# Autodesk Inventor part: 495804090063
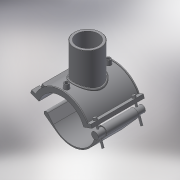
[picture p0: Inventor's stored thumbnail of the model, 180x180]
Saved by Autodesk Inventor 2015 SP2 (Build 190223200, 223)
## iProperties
Created: 2017-07
Part Number: 495804090063
Material: Generic
Description: PLASSON BRANCH SADDLE 90-63
Document SubType Name: Modeling
Designer: KIM
Density: 1 g/cm^3
Appearance: Default
Author: KIM
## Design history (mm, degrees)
derived "495804.ipt"
feature "Solid1::495804.ipt"
feature "Solid2::495804.ipt"
tag "TaggingFeature1"
body "Solid1"
body "Solid2"
other parameters: "d2" = 126, "d3" = 22.5, "d4" = 118, "d5" = 0, "d6" = 0.1, "d8" = 0, "d19" = 6, "d20" = 6, "d21" = 70.8, "d23" = 0, "d24" = 35.4, "d26" = 0, "d27" = 3, "d28" = 3, "d29" = 3, "d31" = 6, "d32" = 0, "d33" = 0, "d34" = 0.6, "d40" = 56.16, "d41" = 69.3, "d43" = 0, "d45" = 0, "d47" = 148, "d48" = 63, "d50" = 0, "d70" = 15, "d72" = 0, "d73" = 6, "d75" = 5, "d76" = 0, "d77" = 4.5, "d78" = 75, "d79" = 15, "d80" = 47.2, "d82" = 5 deg, "d84" = 4, "d85" = 14, "d86" = 0, "d87" = 3, "d88" = 0, "d89" = 1, "d90" = 1, "d91" = 94.4, "d92" = 0, "d93" = 0.5, "d94" = 47.36842, "d96" = 110.16, "d97" = 2.36, "d98" = 0, "d102" = 1.89, "d103" = 50.4, "d105" = 0, "d109" = -31.33333, "d117" = 0.63, "d120" = 140 deg, "d121" = 24.228, "d122" = 20 deg, "d123" = 216, "d124" = 64.8, "d126" = 0, "d143" = 94.5, "d150" = 16.2, "d159" = 3.6, "d161" = 2.25, "d162" = 70.8, "d163" = 0, "d167" = 18, "d168" = 49.09091, "d173" = 1, "d175" = 45, "d176" = 20 deg, "d177" = 6.3, "d178" = 18, "d180" = 0, "d185" = 38.35, "d186" = 38.35, "d187" = 54, "d188" = 5.4, "d189" = 6.3, "d190" = 0, "d191" = 81, "d200" = 9, "d202" = 0, "d216" = 106.2, "d217" = 0, "d221" = 43.66, "d222" = 6.3, "d223" = 3.78, "d224" = 45, "d225" = 3.78, "d227" = 12.96, "d230" = 55.8, "d236" = 20 deg, "d237" = 61, "d238" = 20 deg, "d239" = 6.3, "B_" = 126, "H_" = 94, "L_" = 118, "d_t" = 6, "d_1" = 63, "H_1" = 85, "d1" = 108, "d148" = 2.25, "d160" = 2.25
